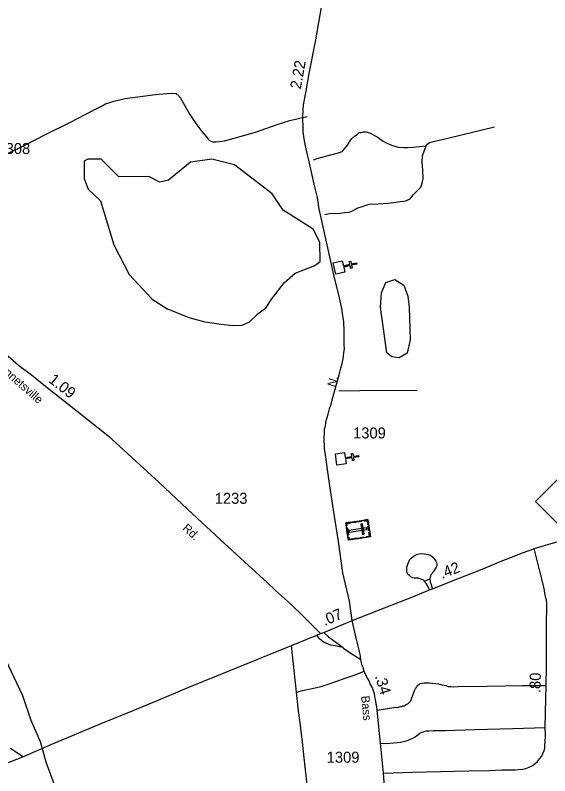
# Model space of a CAD drawing. Extents: x 2093524 to 2270757, y 289120 to 570408.
# Drawn here: x 2177691 to 2183766, y 450232 to 458869 of the extents above; entities that cross this region are included whole.
import ezdxf

# ---------------------------------------------------------------- set-up
doc = ezdxf.new("R2010")
doc.units = 0
for name, color, linetype in [('Exist Cultural Cemetery CELL', 7, 'Continuous'), ('Exist Cultural Church CELL', 7, 'Continuous'), ('Exist Hydrographic Creek Single Shore', 7, 'Continuous'), ('Exist Hydrographic Pond Under 1500 Sq Ft', 7, 'Continuous'), ('Exist Road Non-System Type 51', 7, 'Continuous'), ('Exist Road Primary NC Attributed', 7, 'Continuous'), ('Exist Road Primary NC Mileage Hundredths English Label', 7, 'Continuous'), ('Exist Road Primary NC Shield CELL', 7, 'Continuous'), ('Exist Road Secondary Mileage Hundredths English Label', 7, 'Continuous'), ('Exist Road Secondary Type 51 Attributed', 7, 'Continuous'), ('Exist Road Secondary Type 51 Label', 7, 'Continuous'), ('Exist Road Secondary Type 51 Number Label', 7, 'Continuous')]:
    doc.layers.add(name, color=color, linetype=linetype)

msp = doc.modelspace()

# ---------------------------------------------------------------- linework, layer by layer
at = {"layer": 'Exist Cultural Cemetery CELL'}
for points in [[(2181697.9, 453142), (2181728.2, 452945.2), (2181476.5, 452906.5), (2181446.2, 453103.3)], [(2181451.3, 453070.6), (2181462.7, 453072.3), (2181459.3, 453094.1), (2181499.3, 453100.2), (2181497.6, 453111.2), (2181446.3, 453103.3)], [(2181515.3, 453113.9), (2181558.2, 453120.5), (2181559.9, 453109.3), (2181517.1, 453102.7)], [(2181581.8, 453124.1), (2181624.6, 453130.7), (2181626.3, 453119.5), (2181583.5, 453112.9)], [(2181655.1, 453135.4), (2181656.8, 453124.2), (2181688.6, 453129.1), (2181694.8, 453089), (2181705.8, 453090.7), (2181697.9, 453142)], [(2181466.3, 453048.2), (2181479.2, 452964.4), (2181467.9, 452962.6), (2181455, 453046.5)], [(2181685.5, 453029.8), (2181682.7, 453048.2), (2181482.2, 453017.4), (2181485.1, 452999)], [(2181636.8, 453091.3), (2181618.4, 453088.5), (2181636.3, 452972.1), (2181654.7, 452974.9)], [(2181709.1, 453068.8), (2181717, 453017.5), (2181705.7, 453015.8), (2181697.9, 453067)], [(2181471.4, 452939.3), (2181482.8, 452941), (2181486.1, 452919.3), (2181526.1, 452925.4), (2181527.8, 452914.4), (2181476.5, 452906.5)], [(2181546.2, 452928.7), (2181589, 452935.3), (2181590.7, 452924.1), (2181547.9, 452917.5)], [(2181611.3, 452938.7), (2181654.2, 452945.3), (2181655.9, 452934), (2181613.1, 452927.5)], [(2181685.3, 452938.5), (2181683.6, 452949.8), (2181715.4, 452954.7), (2181709.2, 452994.7), (2181720.2, 452996.4), (2181728.1, 452945.1)]]:
    msp.add_lwpolyline(points, close=True, dxfattribs=at)
at = {"layer": 'Exist Cultural Church CELL'}
for points in [[(2181407.3, 456079.9), (2181420, 456024.4), (2181494.2, 456041.2), (2181487.2, 456072.4), (2181502.8, 456075.9), (2181509.8, 456044.7), (2181568.5, 456058), (2181572, 456042.4), (2181513.4, 456029.1), (2181520.4, 455997.9), (2181504.8, 455994.3), (2181497.8, 456025.6), (2181423.5, 456008.8), (2181436.1, 455952.5), (2181332.3, 455929), (2181303.5, 456056.4)], [(2181434.1, 453904.3), (2181442, 453847.9), (2181517.5, 453858.4), (2181513, 453890.1), (2181528.9, 453892.3), (2181533.3, 453860.6), (2181592.8, 453868.9), (2181595.1, 453853), (2181535.5, 453844.7), (2181539.9, 453813), (2181524.1, 453810.8), (2181519.7, 453842.5), (2181444.3, 453832), (2181452.1, 453774.9), (2181346.6, 453760.2), (2181328.6, 453889.6)]]:
    msp.add_lwpolyline(points, close=True, dxfattribs=at)
at = {"layer": 'Exist Hydrographic Creek Single Shore'}
msp.add_lwpolyline([(2178943.9, 448190), (2178925.9, 448272.3), (2178859, 448372), (2178800, 448579.9), (2178665.1, 448845), (2178554.9, 449185), (2178478, 449527.7), (2178243.1, 449844), (2178048.1, 450376), (2177980, 450616.9), (2177870.9, 450858.5), (2177777, 451139.2), (2177481.9, 451755.2)], dxfattribs=at)
at = {"layer": 'Exist Hydrographic Pond Under 1500 Sq Ft'}
for points in [[(2180533.1, 455538.5), (2180607.5, 455647.6), (2180748, 455829.5), (2180873.3, 455940.7), (2181097, 456025.9), (2181155, 456073.9), (2181154, 456290.5), (2181077.9, 456439.6), (2180735.1, 456656.4), (2180609, 456839.3), (2180182, 457169.3), (2179923.9, 457233.5), (2179682.9, 457198.9), (2179434, 456997.3), (2179333.9, 456973), (2179208.9, 457037.9), (2178867, 457034.9), (2178665.9, 457235.7), (2178516, 457235.4), (2178475, 457210), (2178476, 457016.4), (2178518, 456894.3), (2178661, 456760.2), (2178812.9, 456261.9), (2178987.4, 455925.6), (2179247.4, 455644.5), (2179425, 455531.2)], [(2181843, 455551.7), (2181854, 455717), (2181901.2, 455835.2), (2182003.7, 455866.8), (2182106.2, 455803.7), (2182153.6, 455677.6), (2182168, 455555.1)], [(2180533.1, 455538.5), (2180437.7, 455465.1), (2180349.8, 455384.6), (2180266.7, 455346.4), (2180165, 455341.7), (2180030.5, 455356.2), (2179848, 455383.5), (2179668.8, 455430.8), (2179425, 455531.2)], [(2182054, 454980), (2181971.1, 454988.3), (2181912.1, 455035.3), (2181843, 455551.7)], [(2182168, 455555.1), (2182178, 455180.9), (2182146, 455030.7), (2182054, 454980)]]:
    msp.add_lwpolyline(points, dxfattribs=at)
at = {"layer": 'Exist Road Non-System Type 51'}
for p, q in [((2182341.1, 452442), (2182403, 452470.3)), ((2180886.7, 451182.3), (2180832, 451709.8))]:
    msp.add_line(p, q, dxfattribs=at)
for points in [[(2177472.3, 457232.4), (2177791.3, 457388), (2178042.6, 457519.4), (2178311.5, 457650.8), (2178586.7, 457794.3), (2178672.4, 457834.8), (2178718.3, 457863.1), (2178756.2, 457875.2), (2178810.1, 457893.4), (2178939.9, 457922.3), (2179283.6, 457970.2), (2179415.3, 457978.7), (2179481.3, 457983.3), (2179521.3, 457981.5), (2179535.5, 457969.4), (2179565.6, 457933.7), (2179616.1, 457848.1), (2179674.6, 457742.3), (2179743.1, 457638.9), (2179811.5, 457549.3), (2179859.9, 457491.6), (2179880, 457465.6), (2179898, 457447.9), (2179934.1, 457432.1), (2179974.2, 457432.2), (2180068.2, 457442.8), (2180178, 457471.5), (2180421.5, 457542.7), (2180668.9, 457628.3), (2180810.5, 457675), (2180876.4, 457689.4), (2181010.2, 457720.2)], [(2182359.6, 457385.8), (2182375.3, 457403.9), (2182399.3, 457422.1), (2182475.2, 457442.5), (2182605, 457473.1), (2183138, 457602.1)], [(2181079.1, 457226.8), (2181121, 457240.7), (2181248.7, 457277.5), (2181332.5, 457300.1), (2181374.3, 457310.4), (2181404.4, 457322.3), (2181432.2, 457350.6), (2181467.8, 457392.8), (2181487.6, 457430.8), (2181513.6, 457465.1), (2181547.3, 457495.2), (2181575.2, 457515.3), (2181600.9, 457535.5), (2181622.9, 457537.7), (2181645, 457543.8), (2181674.9, 457543.8), (2181717, 457534.1), (2181803.3, 457486.5), (2181871.6, 457438.9), (2181897.5, 457425.2), (2181967.7, 457391.7), (2182043.7, 457370.2), (2182104, 457366.3), (2182147.9, 457366.4), (2182207.7, 457368.8), (2182359.6, 457385.8)], [(2181210.3, 456605.5), (2181260.4, 456616), (2181382.2, 456620.4), (2181434.1, 456626.9), (2181484.1, 456633.1), (2181524.1, 456647.4), (2181585.8, 456681.6), (2181637.9, 456698), (2181679.6, 456712.2), (2181713.6, 456722.4), (2181815.7, 456728.9), (2181927.3, 456733.5), (2182021.3, 456744.1), (2182067.1, 456754.3), (2182109.2, 456758.7), (2182135.3, 456766.7), (2182177, 456784.9), (2182212.7, 456831.1), (2182258.5, 456875.5), (2182300.3, 456917.6), (2182316, 456963.5), (2182327.6, 457015.8), (2182323.3, 457113.6), (2182314.8, 457199.7), (2182320.3, 457273.8), (2182336.1, 457325.6), (2182359.6, 457385.8)], [(2181369.4, 454601.7), (2181847.1, 454610.5), (2182259.1, 454606.9)], [(2182341.1, 452442), (2182329.2, 452452.1), (2182311.3, 452460), (2182299.3, 452465.8), (2182283, 452471.7), (2182271.2, 452475.5), (2182253.2, 452477.5), (2182235.2, 452477.6), (2182223.1, 452477.5), (2182209, 452481.4), (2182195, 452487.2), (2182185, 452493), (2182171.1, 452505.1), (2182156.9, 452516.8), (2182148.9, 452526.8), (2182142.8, 452548.9), (2182142.8, 452563), (2182142.5, 452580.8), (2182140.3, 452602.8), (2182152.4, 452635), (2182160, 452654.9), (2182175.8, 452689), (2182191.9, 452705.1), (2182207.9, 452719.2), (2182229.8, 452733.2), (2182251.7, 452745.5), (2182279.4, 452751.5), (2182307.3, 452755.6), (2182343.4, 452753.9), (2182383.6, 452746.2), (2182409.6, 452736.1), (2182435.8, 452714.3), (2182455.7, 452692.6), (2182469.9, 452668.7), (2182478.1, 452652.8), (2182480, 452632.7), (2182480.1, 452616.7), (2182474.2, 452600.7), (2182464.3, 452582.5), (2182452.4, 452564.7), (2182442.7, 452552.5), (2182432.6, 452538.6), (2182424.8, 452526.6), (2182414.7, 452514.3), (2182408.8, 452500.3), (2182407, 452488.6), (2182404.9, 452482.4), (2182403, 452470.3)], [(2182397.8, 452342.4), (2182375.6, 452394.4), (2182365.4, 452412.3), (2182341.1, 452442)], [(2182403, 452470.3), (2182403.1, 452460.4), (2182405.1, 452444.3), (2182407.4, 452430.5), (2182409.3, 452422.6), (2182417.4, 452402.4), (2182419.5, 452394.5), (2182421.7, 452386.6), (2182433.8, 452356.5)], [(2181415.7, 451687), (2181327.9, 451706.8), (2181275.6, 451716.4), (2181249.6, 451726.1), (2181225.5, 451736.1), (2181209.5, 451742), (2181191.4, 451753.8), (2181171.3, 451767.7), (2181149.4, 451787.5), (2181139.2, 451799.5), (2181117.1, 451827.5)], [(2181196.8, 451860), (2181249.3, 451810.1), (2181415.7, 451687)], [(2181415.7, 451687), (2181421.9, 451681.3), (2181492.1, 451633.7), (2181616.4, 451552.5)], [(2180886.7, 451182.3), (2180954.7, 451200.9), (2181064.7, 451223.3), (2181162.6, 451246), (2181258.3, 451274.6), (2181346.1, 451305), (2181439.6, 451339.5), (2181553.6, 451380.2), (2181655.1, 451418.5)], [(2181805.6, 450975.6), (2182015.3, 451010.8), (2182037.2, 451009), (2182055.4, 451014.9), (2182069.2, 451016.9), (2182081.4, 451019), (2182093.3, 451025.3), (2182109.1, 451027.3), (2182123, 451035.2), (2182137.3, 451043.4), (2182153.2, 451049.4), (2182168.9, 451063.5), (2182174.9, 451067.6), (2182178.9, 451073.8), (2182185, 451083.8), (2182194.6, 451105.6), (2182232.1, 451207.9), (2182240.3, 451221.8), (2182246, 451231.9), (2182252.2, 451241.9), (2182257.9, 451250), (2182270, 451264.2), (2182281.9, 451272.1), (2182293.9, 451278.1), (2182309.7, 451282.4), (2182319.6, 451284.5), (2182339.7, 451288.4), (2182359.7, 451288.6), (2182381.7, 451288.8), (2182399.7, 451286.8), (2182433.7, 451284.8), (2182469.7, 451279.2), (2182501.8, 451275.3), (2182543.9, 451265.6), (2182585.7, 451255.9), (2182611.7, 451245.9), (2182627.8, 451244.2), (2182641.9, 451246.2), (2182676, 451242.3), (2182725.9, 451244.6), (2183053.6, 451248.5), (2183453.4, 451258.9), (2183723.3, 451258.1)], [(2181777.6, 448520.3), (2181629.1, 448593.5), (2181518.6, 448661), (2181438.6, 448712.4), (2181336.2, 448773.8), (2181263.9, 448831.4), (2181187.5, 448883.1), (2181167.5, 448900.9), (2181149.5, 448920.6), (2181133.5, 448938.6), (2181127.3, 448956.5), (2181121.1, 448972.7), (2181119, 449002.6), (2181102, 449166.2), (2181087.2, 449344.3), (2181072, 449538.2), (2181046.8, 449785.7), (2181013, 450099.6), (2180975.1, 450435.3), (2180956, 450613.1), (2180931, 450804.8), (2180908, 450998.5), (2180886.7, 451182.3)], [(2181841.8, 450601.9), (2181903.7, 450598.4), (2181993.7, 450604.8), (2182029.6, 450609), (2182071.6, 450613.1), (2182101.6, 450619.4), (2182133.6, 450629.6), (2182143.6, 450633.6), (2182175.2, 450643.8), (2182207.3, 450657.9), (2182235.2, 450674.1), (2182253.2, 450688.2), (2182268.9, 450700.3), (2182288.9, 450716.3), (2182314.7, 450728.6), (2182338.8, 450736.7), (2182364.8, 450740.7), (2182392.7, 450740.8), (2182442.6, 450745.4), (2182576.5, 450748), (2182912.6, 450756), (2183346.1, 450768.3), (2183712.1, 450778.4)], [(2177776.2, 450445.4), (2177635.7, 450540.4)]]:
    msp.add_lwpolyline(points, dxfattribs=at)
at = {"layer": 'Exist Road Primary NC Attributed'}
for points in [[(2183588.7, 452812.9), (2183680.5, 452839.3), (2183782.4, 452870.1), (2184007.8, 452935.1), (2184233.4, 452996.5), (2184385.2, 453029.2), (2184614.7, 453072.5), (2184828.4, 453113.5), (2185090.1, 453157.2), (2185343.9, 453206.5), (2185563.6, 453247.7), (2186080.5, 453352.7)], [(2181520, 451995.6), (2181887, 452139.8), (2182218.2, 452269.3), (2182397.8, 452342.4), (2182433.8, 452356.5), (2182629.2, 452433.6), (2182822.6, 452508.8), (2183014.1, 452585.6), (2183213.6, 452668.9), (2183343.4, 452717.5), (2183445, 452758.1), (2183542.7, 452792.5), (2183555, 452796.6), (2183588.7, 452812.9)], [(2181159.2, 451847.6), (2181196.8, 451860), (2181520, 451995.6)], [(2177347.4, 450278.9), (2177776.2, 450445.4), (2178107.4, 450589.1), (2178649.9, 450818), (2179030.6, 450974.1), (2179314, 451091.7), (2179665, 451239.5), (2179980.1, 451365.4), (2180325.1, 451507.1), (2180832, 451709.8), (2181117.1, 451827.5), (2181159.2, 451847.6)]]:
    msp.add_lwpolyline(points, dxfattribs=at)
at = {"layer": 'Exist Road Primary NC Shield CELL'}
msp.add_lwpolyline([(2183603.6, 453348), (2183936.6, 453681), (2184269.5, 453348), (2183936.6, 453015)], close=True, dxfattribs=at)
at = {"layer": 'Exist Road Secondary Type 51 Attributed'}
for points in [[(2181520, 451995.6), (2181490.4, 452214.5), (2181415.1, 452536.4), (2181363.2, 452892.1), (2181315.6, 453201.7), (2181265.6, 453525.1), (2181242.9, 453683), (2181215.9, 453876.8), (2181205.6, 453948.8), (2181205.1, 453990.8), (2181203, 454032.5), (2181202.5, 454076.8), (2181204.3, 454116.8), (2181204.2, 454144.7), (2181206.1, 454170.5), (2181215.8, 454200.5), (2181219.7, 454244.7), (2181229.5, 454276.7), (2181237.5, 454300.8), (2181247.1, 454336.7), (2181262.8, 454399), (2181276.7, 454441), (2181302.1, 454542.9), (2181317.6, 454597), (2181372.5, 454785.2), (2181390.4, 454859.3), (2181407.9, 454915.4), (2181417.8, 454965.3), (2181425.1, 455035.4), (2181431, 455083.5), (2181430.7, 455121.6), (2181430.3, 455197.3), (2181429.6, 455309.5), (2181425.3, 455357.5), (2181425.2, 455387.4), (2181419, 455435.4), (2181414.8, 455457.4), (2181408.7, 455481.2), (2181400.7, 455538.7), (2181375.9, 455658.3), (2181312.5, 455920), (2181158.5, 456600.8), (2181144.4, 456666.7), (2181125.4, 456798.6), (2181086.8, 456950.2), (2181027.3, 457222), (2181010.8, 457283.7), (2180990.2, 457385.5), (2180975.7, 457465.5), (2180961.6, 457543.5), (2180963.2, 457577.3), (2180963, 457617.3), (2180958.6, 457675.4), (2180958.4, 457715.5), (2180962, 457793.5), (2180965.7, 457851.4), (2180992.8, 457989.3), (2181031.5, 458205.7), (2181105.5, 458590), (2181190.6, 459074)], [(2181159.2, 451847.6), (2180976.2, 452032.7), (2180817.2, 452185.8), (2180650.3, 452336.7), (2180552.1, 452425.9), (2180296.7, 452660.7), (2180021.6, 452914.8), (2179653.8, 453254.8), (2179326, 453560.8), (2179060.9, 453805.2), (2178835.8, 454011.8), (2178787.5, 454055.7), (2178763.6, 454077.5), (2178396.1, 454367.3), (2178052.5, 454637.3), (2177874, 454780.2), (2177727.3, 454891.4), (2177548.4, 455048.2), (2177482.3, 455107.9), (2177309.4, 455270.8), (2177206.9, 455376.2), (2177146.4, 455438), (2177058.4, 455515.5), (2176883.4, 455687.4)], [(2181875.7, 450262.4), (2182207.6, 450274.2), (2182523.3, 450281.9), (2182845.2, 450289.6), (2183081.1, 450293.1), (2183220.9, 450297.8), (2183316.8, 450300.2), (2183372.9, 450300.7), (2183406.7, 450303), (2183456.9, 450305.3), (2183494.9, 450315.3), (2183532.5, 450329.7), (2183570.6, 450347.6), (2183600.3, 450370), (2183626.4, 450396), (2183649.9, 450424.1), (2183675.8, 450454.4), (2183687.5, 450486.3), (2183701.6, 450518.5), (2183707.4, 450544.3), (2183711, 450578.3), (2183713.1, 450614.4), (2183716.6, 450692.4), (2183712.1, 450778.4), (2183717, 450944.3), (2183722.1, 451114.4), (2183723.3, 451258.1), (2183728.2, 451468.2), (2183728.8, 451730), (2183729.5, 451959.9), (2183730.2, 452145.9), (2183730, 452183.9), (2183727.9, 452227.9), (2183717.9, 452265.8), (2183707.2, 452337.6), (2183690.9, 452407.8), (2183643.9, 452585.2), (2183588.7, 452812.9)], [(2181875.7, 450262.4), (2181841.8, 450601.9), (2181805.6, 450975.6), (2181799.3, 451019.7), (2181791.3, 451045.4), (2181789.1, 451081.6), (2181782.8, 451113.5), (2181778.7, 451137.5), (2181772.7, 451163.3), (2181758.5, 451209.1), (2181748.2, 451237.2), (2181726, 451275.1), (2181713.9, 451311.1), (2181693.8, 451339), (2181671.4, 451382.8), (2181655.1, 451418.5), (2181647, 451442.6), (2181643.1, 451460.4), (2181635, 451482.5), (2181626.8, 451514.5), (2181616.4, 451552.5), (2181612, 451612.2), (2181569.2, 451780.1), (2181520, 451995.6)], [(2181892.9, 450008.5), (2181875.7, 450262.4)]]:
    msp.add_lwpolyline(points, dxfattribs=at)

# ---------------------------------------------------------------- texts
at = {"layer": 'Exist Road Primary NC Mileage Hundredths English Label'}
for s, rotation, p in [('.42', 21.24389, (2182540.8, 452466.3)), ('.07', 22.75693, (2181207.2, 451932.2))]:
    msp.add_text(s, height=125, rotation=rotation, dxfattribs=at).set_placement(p)
at = {"layer": 'Exist Road Secondary Mileage Hundredths English Label'}
for s, rotation, p in [('2.22', 79.84232, (2180935.5, 458023.8)), ('1.09', 321.84649, (2178060.7, 454710.3)), ('.80', 88.67645, (2183658.8, 451169.9)), ('.34', 287.16835, (2181776.4, 451362.7))]:
    msp.add_text(s, height=125, rotation=rotation, dxfattribs=at).set_placement(p)
at = {"layer": 'Exist Road Secondary Type 51 Label'}
for s, rotation, p in [('Bonnetsville', 318.77557, (2177441.1, 454901)), ('N.', 72.64483, (2181324.5, 454639.3)), ('Rd.', 317.26263, (2179585.7, 453033.9)), ('Bass', 275.52685, (2181621.1, 451136.7))]:
    msp.add_text(s, height=95, rotation=rotation, dxfattribs=at).set_placement(p)
at = {"layer": 'Exist Road Secondary Type 51 Number Label'}
for s, p in [('1308', (2177489.1, 457292.9)), ('1309', (2181530.5, 454062.6)), ('1233', (2179958.1, 453320.4)), ('1309', (2181230.4, 450380.5))]:
    msp.add_text(s, height=125, dxfattribs=at).set_placement(p)

doc.saveas('drawing.dxf')
